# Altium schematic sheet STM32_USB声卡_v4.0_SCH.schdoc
size 436 x 307 mm
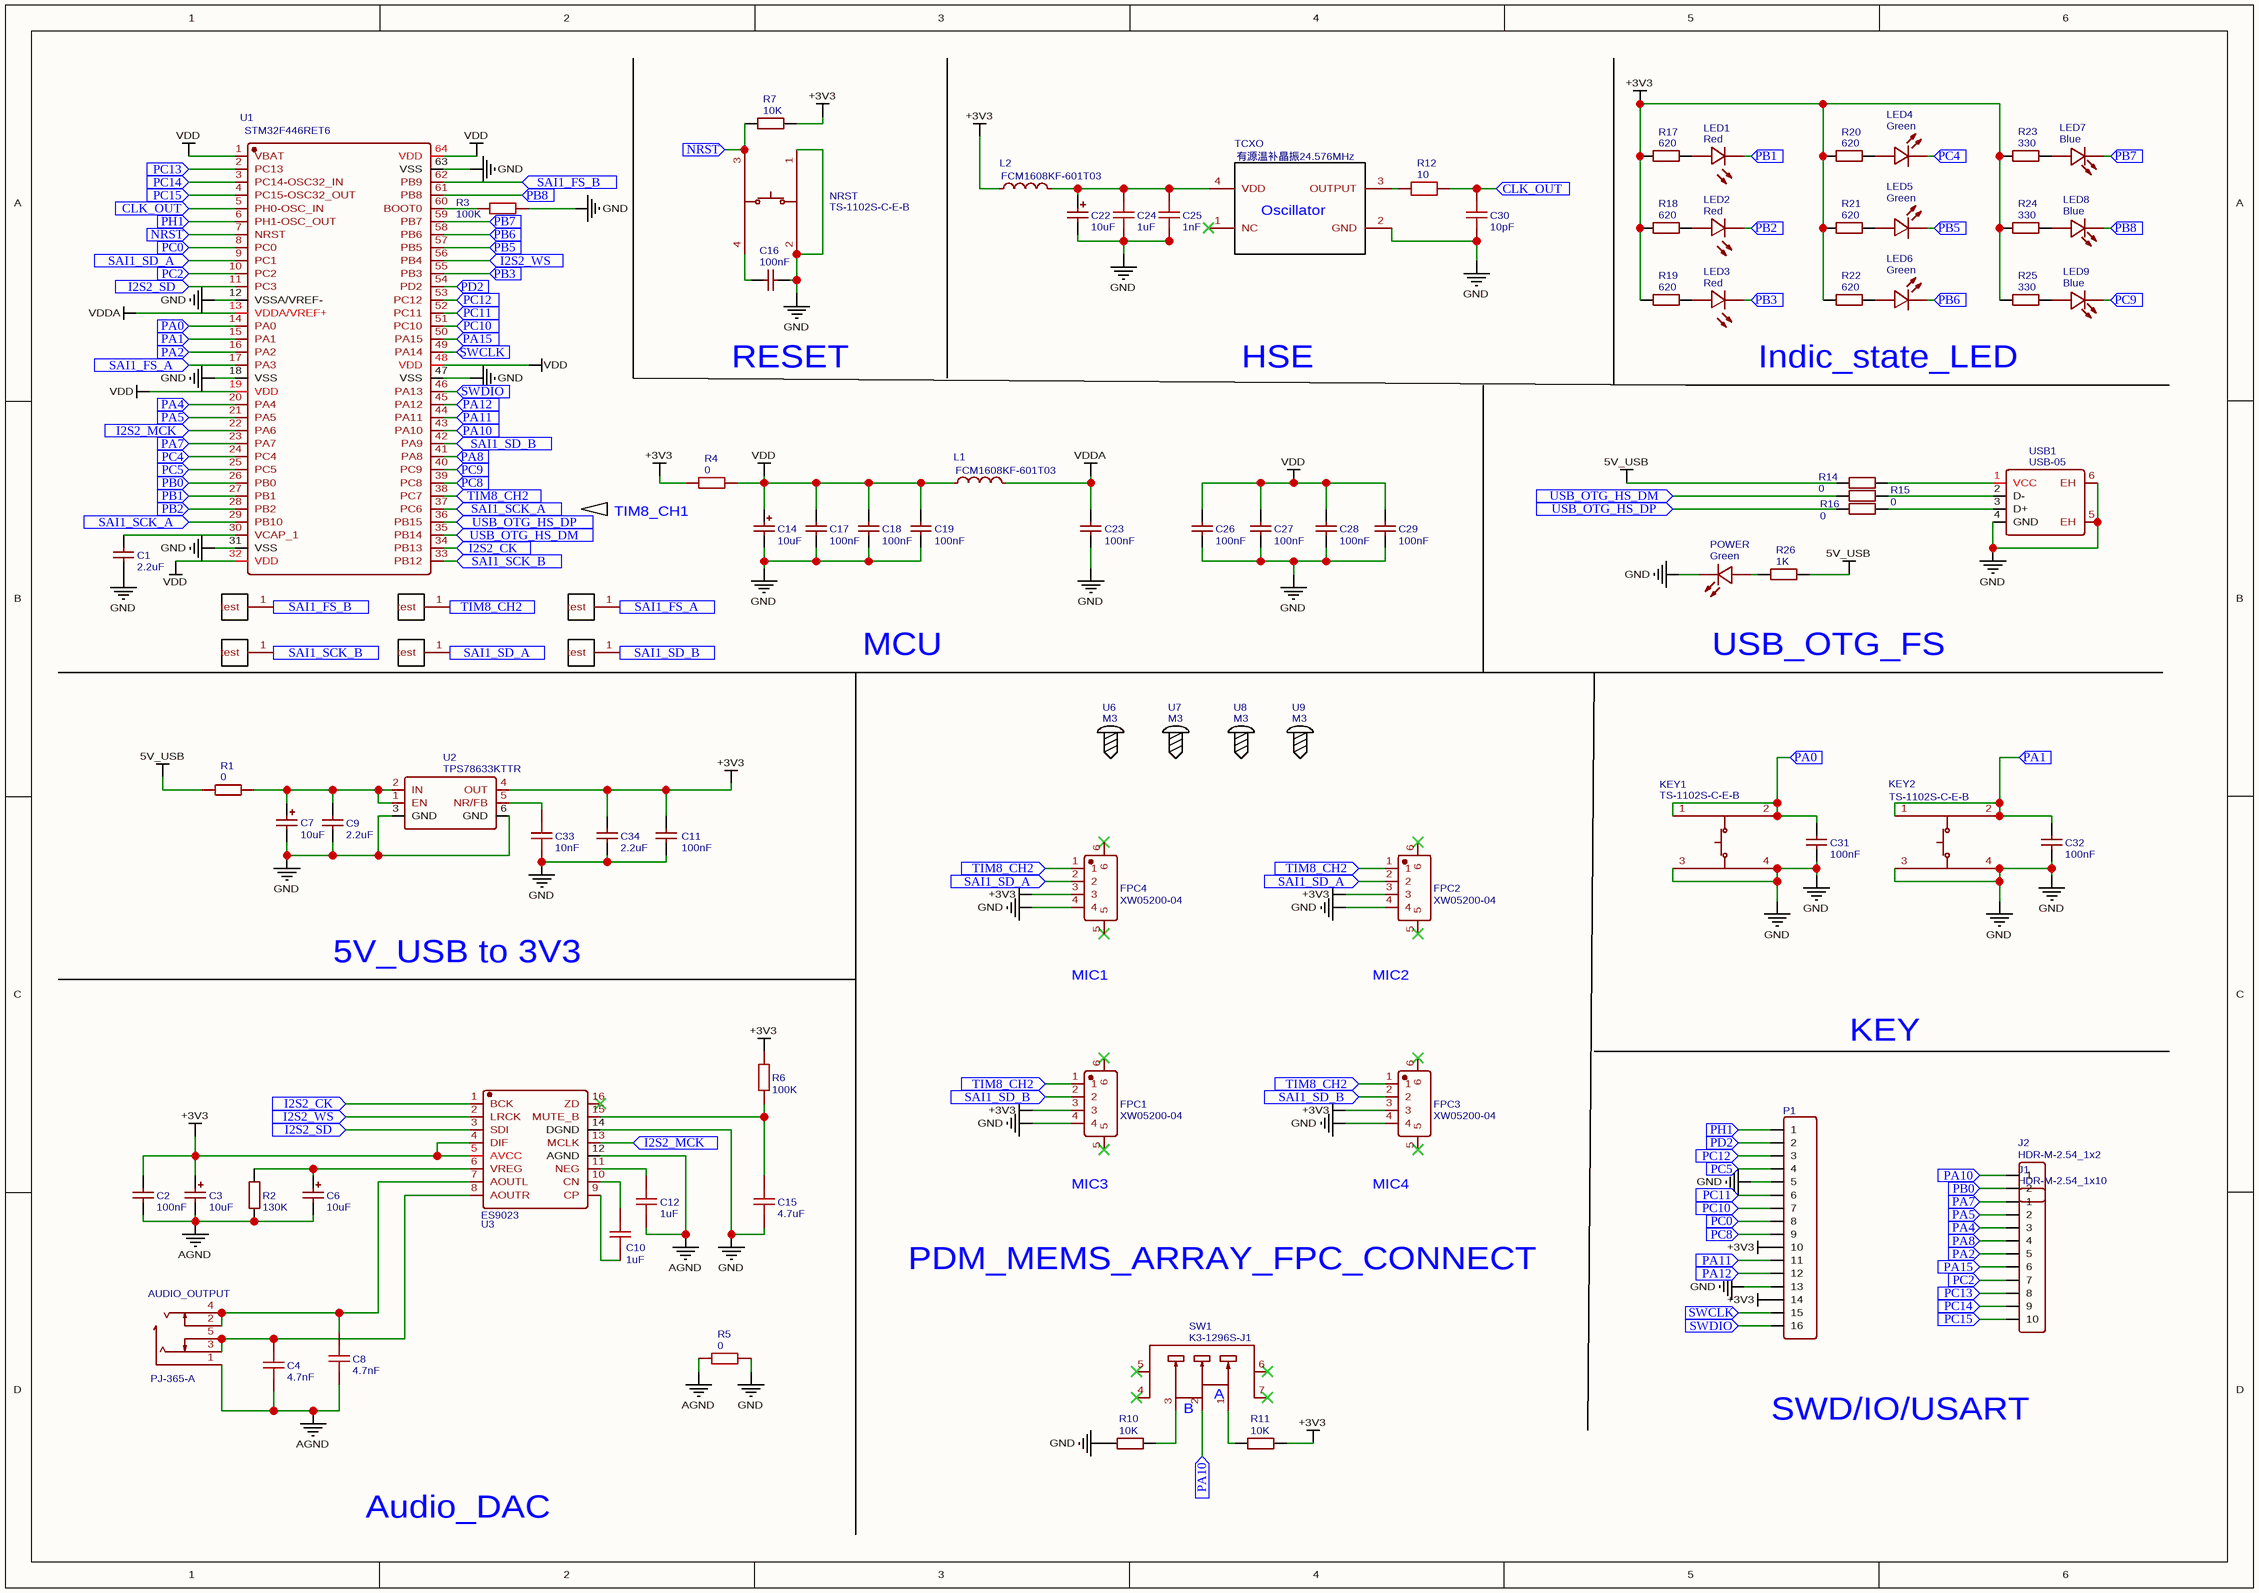
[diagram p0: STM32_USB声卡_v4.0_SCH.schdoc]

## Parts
AUDIO_OUTPUT  PJ-365-A  [AUDIO-SMD_PJ-365-A]
C1  2.2uF  [C0805]
C2  100nF  [C0805]
C3  10uF  [CAP-SMD_L3.2-W1.6]
C4  4.7nF  [C0805]
C6  10uF  [CAP-SMD_L3.2-W1.6]
C7  10uF  [CAP-SMD_L3.2-W1.6]
C8  4.7nF  [C0805]
C9  2.2uF  [C0805]
C10  1uF  [C0805]
C11  100nF  [C0805]
C12  1uF  [C0805]
C14  10uF  [CAP-SMD_L3.2-W1.6]
C15  4.7uF  [C0805]
C16  100nF  [C0805]
C17  100nF  [C0805]
C18  100nF  [C0805]
C19  100nF  [C0805]
C22  10uF  [CAP-SMD_L3.2-W1.6]
C23  100nF  [C0805]
C24  1uF  [C0805]
C25  1nF  [C0805]
C26  100nF  [C0805]
C27  100nF  [C0805]
C28  100nF  [C0805]
C29  100nF  [C0805]
C30  10pF  [C0805]
C31  100nF  [C0805]
C32  100nF  [C0805]
C33  10nF  [C0805]
C34  2.2uF  [C0805]
FPC1  XW05200-04  [FPC-SMD_4P-P0.50_XW05200-04]
FPC2  XW05200-04  [FPC-SMD_4P-P0.50_XW05200-04]
FPC3  XW05200-04  [FPC-SMD_4P-P0.50_XW05200-04]
FPC4  XW05200-04  [FPC-SMD_4P-P0.50_XW05200-04]
J1  HDR-M-2.54_1x10  [HDR-M-2.54_1X10]
J2  HDR-M-2.54_1x2  [HDR-M-2.54_1X2]
KEY1  TS-1102S-C-E-B  [KEY-SMD_4P-L6.0-W6.0-P4.50-LS8.6]
KEY2  TS-1102S-C-E-B  [KEY-SMD_4P-L6.0-W6.0-P4.50-LS8.6]
L1  FCM1608KF-601T03  [L0603]
L2  FCM1608KF-601T03  [L0603]
LED1  Red  [LED0805-R-RD]
LED2  Red  [LED0805-R-RD]
LED3  Red  [LED0805-R-RD]
LED4  Green  [LED0805-FD]
LED5  Green  [LED0805-FD]
LED6  Green  [LED0805-FD]
LED7  Blue  [LED0805-R-RD]
LED8  Blue  [LED0805-R-RD]
LED9  Blue  [LED0805-R-RD]
NRST  TS-1102S-C-E-B  [KEY-SMD_4P-L6.0-W6.0-P4.50-LS8.6]
P1  Header-Female-2.54_1x16  [HDR-16X1/2.54]  (value not drawn)
POWER  Green  [LED0805-FD]
R1  0  [R0805]
R2  130K  [R0805]
R3  100K  [R0805]
R4  0  [R0805]
R5  0  [R0805]
R6  100K  [R0805]
R7  10K  [R0805]
R10  10K  [R0805]
R11  10K  [R0805]
R12  10  [R0805]
R14  0  [R0603]
R15  0  [R0603]
R16  0  [R0603]
R17  620  [R0805]
R18  620  [R0805]
R19  620  [R0805]
R20  620  [R0805]
R21  620  [R0805]
R22  620  [R0805]
R23  330  [R0805]
R24  330  [R0805]
R25  330  [R0805]
R26  1K  [R0805]
SW1  K3-1296S-J1  [SW-SMD_K3-1296S-J1]
TCXO  有源温补晶振24.576MHz  [TCXO]
U1  STM32F446RET6  [LQFP-64_L10.0-W10.0-P0.50-LS12.0-BL]
U2  TPS78633KTTR  [TO-263-5_L10.2-W9.9-P1.70-LS14.4-TL]
U3  ES9023  [SOP-16_150MIL]
U4  test  [TEST]  (value not drawn)
U5  test  [TEST]  (value not drawn)
U6  M3  [M3-3]
U7  M3  [M3-3]
U8  M3  [M3-3]
U9  M3  [M3-3]
U10  test  [TEST]  (value not drawn)
U11  test  [TEST]  (value not drawn)
U12  test  [TEST]  (value not drawn)
U13  test  [TEST]  (value not drawn)
USB1  USB-05  [USB-A-TH_48037-0001]

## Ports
CLK_OUT (in), I2S2_CK (in), I2S2_MCK (in), I2S2_SD (in), I2S2_WS (in), NRST (in), PA0 (in), PA1 (in), PA2 (in), PA4 (in), PA5 (in), PA7 (in), PA8 (in), PA10 (in), PA11 (in), PA12 (in), PA15 (in), PB0 (in), PB1 (in), PB2 (in), PB3 (in), PB5 (in), PB6 (in), PB7 (in), PB8 (in), PC0 (in), PC2 (in), PC4 (in), PC5 (in), PC8 (in), PC9 (in), PC10 (in), PC11 (in), PC12 (in), PC13 (in), PC14 (in), PC15 (in), PD2 (in), PH1 (in), SAI1_FS_A (in), SAI1_FS_B (in), SAI1_SCK_A (in), SAI1_SCK_B (in), SAI1_SD_A (in), SAI1_SD_B (in), SWCLK (in), SWDIO (in), TIM8_CH2 (in), USB_OTG_HS_DM (in), USB_OTG_HS_DP (in)

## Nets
5V_USB: R1.1 R14.1 R26.2
+3V3: C2.2 C3.1 C11.1 C34.1 FPC1.3 FPC2.3 FPC3.3 FPC4.3 L2.1 P1.10 P1.14 R4.1 R6.2 R7.1 R11.1 R17.1 R18.1 R19.1 R20.1 R21.1 R22.1 R23.1 R24.1 R25.1 U2.4(OUT) U3.4(DIF) U3.5(AVCC)
AGND: AUDIO_OUTPUT.1 C2.1 C3.2 C4.1 C6.2 C8.1 C12.1 R2.1 R5.1 U3.12(AGND)
GND: C1.2 C7.2 C9.2 C11.2 C14.2 C15.1 C16.1 C17.1 C18.1 C19.1 C22.2 C23.1 C24.1 C25.2 C26.1 C27.1 C28.1 C29.1 C30.2 C31.1 C32.1 C33.1 C34.2 FPC1.4 FPC2.4 FPC3.4 FPC4.4 KEY1.3 KEY1.4 KEY2.3 KEY2.4 NRST.1 NRST.2 P1.5 P1.13 POWER.2(K) R3.1 R5.2 R10.1 TCXO.2(GND) U1.12(VSSA/VREF-) U1.18(VSS) U1.31(VSS) U1.47(VSS) U1.63(VSS) U2.3(GND) U2.6(GND) U3.14(DGND) USB1.4(GND) USB1.5(EH) USB1.6(EH)
VDD: C14.1 C17.2 C18.2 C19.2 C26.2 C27.2 C28.2 C29.2 L1.1 R4.2 U1.1(VBAT) U1.19(VDD) U1.32(VDD) U1.48(VDD) U1.64(VDD)
VDDA: C23.2 L1.2 U1.13(VDDA/VREF+)
CLK_OUT: C30.1 R12.2 U1.5(PH0-OSC_IN) ; port CLK_OUT
I2S2_CK: U1.34(PB13) U3.1(BCK) ; port I2S2_CK
I2S2_MCK: U1.22(PA6) U3.13(MCLK) ; port I2S2_MCK
I2S2_SD: U1.11(PC3) U3.3(SDI) ; port I2S2_SD
I2S2_WS: U1.56(PB4) U3.2(LRCK) ; port I2S2_WS
NRST: NRST.3 R7.2 U1.7(NRST) ; port NRST
PA0: C31.2 KEY1.1 KEY1.2 U1.14(PA0) ; port PA0
PA1: C32.2 KEY2.1 KEY2.2 U1.15(PA1) ; port PA1
PA2: J1.5 U1.16(PA2) ; port PA2
PA4: J1.3 U1.20(PA4) ; port PA4
PA5: J1.2 U1.21(PA5) ; port PA5
PA7: J1.1 U1.23(PA7) ; port PA7
PA8: J1.4 U1.41(PA8) ; port PA8
PA10: J2.1 SW1.2 U1.43(PA10) ; port PA10
PA11: P1.11 U1.44(PA11) ; port PA11
PA12: P1.12 U1.45(PA12) ; port PA12
PA15: J1.6 U1.50(PA15) ; port PA15
PB0: J2.2 U1.26(PB0) ; port PB0
PB1: LED1.2(-) U1.27(PB1) ; port PB1
PB2: LED2.2(-) U1.28(PB2) ; port PB2
PB3: LED3.2(-) U1.55(PB3) ; port PB3
PB5: LED5.2(K) U1.57(PB5) ; port PB5
PB6: LED6.2(K) U1.58(PB6) ; port PB6
PB7: LED7.2(C) U1.59(PB7) ; port PB7
PB8: LED8.2(C) U1.61(PB8) ; port PB8
PC0: P1.8 U1.8(PC0) ; port PC0
PC2: J1.7 U1.10(PC2) ; port PC2
PC4: LED4.2(K) U1.24(PC4) ; port PC4
PC5: P1.4 U1.25(PC5) ; port PC5
PC8: P1.9 U1.39(PC8) ; port PC8
PC9: LED9.2(C) U1.40(PC9) ; port PC9
PC10: P1.7 U1.51(PC10) ; port PC10
PC11: P1.6 U1.52(PC11) ; port PC11
PC12: P1.3 U1.53(PC12) ; port PC12
PC13: J1.8 U1.2(PC13) ; port PC13
PC14: J1.9 U1.3(PC14-OSC32_IN) ; port PC14
PC15: J1.10 U1.4(PC15-OSC32_OUT) ; port PC15
PD2: P1.2 U1.54(PD2) ; port PD2
PH1: P1.1 U1.6(PH1-OSC_OUT) ; port PH1
SAI1_FS_A: U1.17(PA3) U12.1(test) ; port SAI1_FS_A
SAI1_FS_B: U1.62(PB9) U4.1(test) ; port SAI1_FS_B
SAI1_SCK_A: U1.29(PB10) U1.37(PC6) ; port SAI1_SCK_A
SAI1_SCK_B: U1.33(PB12) U5.1(test) ; port SAI1_SCK_B
SAI1_SD_A: FPC2.2 FPC4.2 U1.9(PC1) U11.1(test) ; port SAI1_SD_A
SAI1_SD_B: FPC1.2 FPC3.2 U1.42(PA9) U13.1(test) ; port SAI1_SD_B
SWCLK: P1.15 U1.49(PA14) ; port SWCLK
SWDIO: P1.16 U1.46(PA13) ; port SWDIO
TIM8_CH2: FPC1.1 FPC2.1 FPC3.1 FPC4.1 U1.38(PC7) U10.1(test) ; port TIM8_CH2
USB_OTG_HS_DM: R15.1 U1.35(PB14) ; port USB_OTG_HS_DM
USB_OTG_HS_DP: R16.1 U1.36(PB15) ; port USB_OTG_HS_DP
NetAUDIO_OUTPUT_2: AUDIO_OUTPUT.2 AUDIO_OUTPUT.4 C8.2 U3.7(AOUTL)
NetAUDIO_OUTPUT_3: AUDIO_OUTPUT.3 AUDIO_OUTPUT.5 C4.2 U3.8(AOUTR)
NetC1_1: C1.1 U1.30(VCAP_1)
NetC6_1: C6.1 R2.2 U3.6(VREG)
NetC7_1: C7.1 C9.1 R1.2 U2.1(EN) U2.2(IN)
NetC10_1: C10.1 U3.9(CP)
NetC10_2: C10.2 U3.10(CN)
NetC12_2: C12.2 U3.11(NEG)
NetC15_2: C15.2 R6.1 U3.15(MUTE_B)
NetC16_2: C16.2 NRST.4
NetC22_1: C22.1 C24.2 C25.1 L2.2 TCXO.4(VDD)
NetC33_2: C33.2 U2.5(NR/FB)
NetLED1_1: LED1.1(+) R17.2
NetLED2_1: LED2.1(+) R18.2
NetLED3_1: LED3.1(+) R19.2
NetLED4_1: LED4.1(A) R20.2
NetLED5_1: LED5.1(A) R21.2
NetLED6_1: LED6.1(A) R22.2
NetLED7_1: LED7.1(A) R23.2
NetLED8_1: LED8.1(A) R24.2
NetLED9_1: LED9.1(A) R25.2
NetPOWER_1: POWER.1(A) R26.1
NetR3_2: R3.2 U1.60(BOOT0)
NetR10_2: R10.2 SW1.3
NetR11_2: R11.2 SW1.1
NetR12_1: R12.1 TCXO.3(OUTPUT)
NetR14_2: R14.2 USB1.1(VCC)
NetR15_2: R15.2 USB1.2(D-)
NetR16_2: R16.2 USB1.3(D+)

Not connected (* = marked no-connect by the designer): FPC1 5* 6*; FPC2 5* 6*; FPC3 5* 6*; FPC4 5* 6*; SW1 4* 5* 6* 7*; TCXO 1(NC)*; U3 16(ZD)*

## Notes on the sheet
- RESET
- HSE
- Indic_state_LED
- (near R4) TIM8_CH1
- MCU
- USB_OTG_FS
- 5V_USB to 3V3
- (near FPC4) MIC1
- (near FPC2) MIC2
- KEY
- (near FPC1) MIC3
- (near FPC3) MIC4
- PDM_MEMS_ARRAY_FPC_CONNECT
- SWD/IO/USART
- Audio_DAC

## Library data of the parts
AUDIO_OUTPUT = PJ-365-A: BOM_Manufacturer: HRO
C1 C9 C34 = 2.2uF: BOM_Manufacturer: SAMSUNG; BOM_Manufacturer Part: CL21A225KAFNNNE; nameAlias: Capacitance
C2 C11 C16-C19 C23 C26-C29 C31 C32 = 100nF: BOM_Manufacturer: YAGEO; BOM_Manufacturer Part: CC0805JRX7R9BB104; nameAlias: Capacitance
C3 C6 C7 C14 C22 = 10uF: BOM_Manufacturer: Xiangyee; BOM_Manufacturer Part: CA45-A010K106T; nameAlias: Capacitance; SMT Type: Extend
C4 C8 = 4.7nF: BOM_Manufacturer: Huaxin S&T; BOM_Manufacturer Part: 0805B472J500CT; nameAlias: Capacitance; Contributor: LCSC
C10 C12 C24 = 1uF: BOM_Manufacturer: CCTC; BOM_Manufacturer Part: TCC0805X7R105K500DTB; nameAlias: Capacitance; Contributor: LCSC
C15 = 4.7uF: BOM_Manufacturer: Taiyo Yuden; BOM_Manufacturer Part: TMK212BJ475KG-T; nameAlias: Capacitance; Contributor: LCSC
C25 = 1nF: BOM_Manufacturer: WTC; BOM_Manufacturer Part: 0805N102J500; nameAlias: Capacitance; Contributor: LCSC
C30 = 10pF: BOM_Manufacturer: FH; BOM_Manufacturer Part: 0805CG100J500NT; nameAlias: Capacitance; Contributor: LCSC
C33 = 10nF: BOM_Manufacturer: YAGEO; BOM_Manufacturer Part: CC0805JRX7R9BB103; nameAlias: Capacitance
FPC1-FPC4 = XW05200-04: BOM_Manufacturer: MINTRON; Contributor: LCSC
J1 = HDR-M-2.54_1x10: Contributor: LCEDA_Lib
J2 = HDR-M-2.54_1x2: Contributor: LCEDA_Lib
KEY1 KEY2 NRST = TS-1102S-C-E-B: BOM_Manufacturer: XKB Enterprise; Contributor: LCSC
L1 L2 = FCM1608KF-601T03: BOM_Manufacturer: TAITEC; Contributor: LCSC
LED1-LED3 = Red: BOM_Manufacturer: EKINGLUX; BOM_Manufacturer Part: E6C0805URAC1UDA; Contributor: LCSC; SMT Type: Extend
LED4-LED6 POWER = Green: BOM_Manufacturer: NATIONSTAR; BOM_Manufacturer Part: FC-2012UGK-520D5; SMT Type: Extend
LED7-LED9 = Blue: BOM_Manufacturer: Orient; BOM_Manufacturer Part: ORH-B35A; Contributor: LCSC
P1 = Header-Female-2.54_1x16: BOM_Manufacturer: BOOMELE; BOM_Manufacturer Part: Female header1*16P pitch 2.54mm
R1 R4 R5 = 0: BOM_Manufacturer: Guangdong Fenghua Advanced Tech; BOM_Manufacturer Part: RS-05000FT; nameAlias: Resistance (Ohms); Contributor: LCSC
R2 = 130K: BOM_Manufacturer: UniOhm; BOM_Manufacturer Part: 0805W8F1303T5E; nameAlias: Resistance (Ohms); SMT Type: Extend
R3 R6 = 100K: BOM_Manufacturer: Uniroyal Elec; BOM_Manufacturer Part: 0805W8F1003T5E; nameAlias: Resistance (Ohms); Contributor: LCSC
R7 R10 R11 = 10K: BOM_Manufacturer: FH; BOM_Manufacturer Part: RS-05K1002FT; nameAlias: Resistance (Ohms)
R12 = 10: BOM_Manufacturer: PANASONIC; BOM_Manufacturer Part: ERJ6RED10R0V; nameAlias: Resistance (Ohms); Contributor: LCSC
R14-R16 = 0: BOM_Manufacturer: YAGEO; BOM_Manufacturer Part: RC0603FR-070RL; nameAlias: Resistance (Ohms)
R17-R22 = 620: BOM_Manufacturer: FH; BOM_Manufacturer Part: RS-05K621JT; nameAlias: Resistance (Ohms); Contributor: LCSC
R23-R25 = 330: BOM_Manufacturer: UniOhm; BOM_Manufacturer Part: 0805W8J0331T5E; nameAlias: Resistance (Ohms)
R26 = 1K: BOM_Manufacturer: UniOhm; BOM_Manufacturer Part: 0805W8J0102T5E; nameAlias: Resistance (Ohms)
SW1 = K3-1296S-J1: BOM_Manufacturer: Korean Hroparts Elec; Contributor: LCSC
TCXO = 有源温补晶振24.576MHz: Contributor: WZS_123
U1 = STM32F446RET6: BOM_Manufacturer: STMicroelectronics; subpart_no: 1; SMT Type: Extend
U2 = TPS78633KTTR: BOM_Manufacturer: Texas Instruments; Contributor: LCSC
U3 = ES9023: Contributor: SaceLacg
U4 U5 U10-U13 = test: Contributor: Ssu7828
U6-U9 = M3: Contributor: ww22350777
USB1 = USB-05: BOM_Manufacturer: SOFNG; Contributor: LCSC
